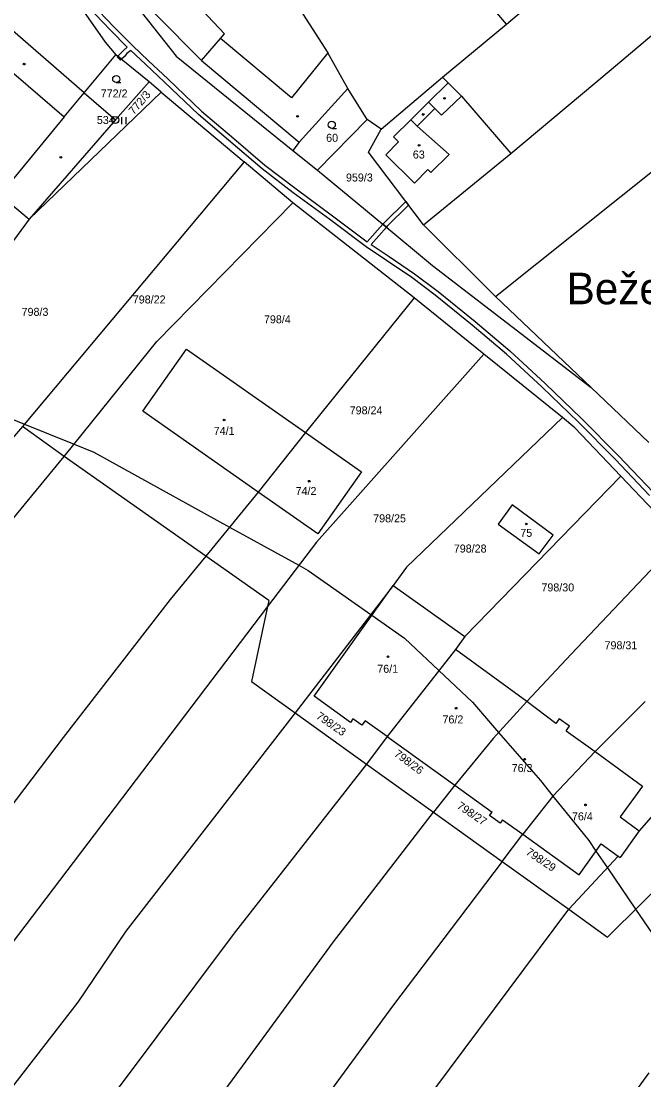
# Model space of a CAD drawing. Extents: x -749173 to -746119, y -1132678 to -1130338.
# Drawn here: x -747826.9 to -747694.7, y -1131323.7 to -1131098.8 of the extents above; entities that cross this region are included whole.
import ezdxf

# ---------------------------------------------------------------- set-up
doc = ezdxf.new("R2010")
doc.units = 0
for name, color, linetype in [('Vrstva 1', 7, 'Continuous'), ('Vrstva 15', 7, 'Continuous'), ('Vrstva 17', 7, 'Continuous'), ('Vrstva 18', 7, 'Continuous'), ('Vrstva 19', 7, 'Continuous'), ('Vrstva 24', 7, 'Continuous'), ('Vrstva 25', 7, 'Continuous'), ('Vrstva 3', 7, 'Continuous'), ('Vrstva 30', 7, 'Continuous'), ('Vrstva 37', 7, 'Continuous'), ('Vrstva 4', 7, 'Continuous'), ('Vrstva 52', 7, 'Continuous'), ('Vrstva 6', 7, 'Continuous')]:
    doc.layers.add(name, color=color, linetype=linetype)

msp = doc.modelspace()

# ---------------------------------------------------------------- linework, layer by layer
at = {"layer": 'Vrstva 1'}
for points in [[(-747702.08, -1131109.45), (-747662.38, -1131075.87)], [(-747723.91, -1131099.47), (-747741.27, -1131078.96)], [(-747723.91, -1131099.47), (-747702.76, -1131081.57)], [(-747774.37, -1131086), (-747761.8, -1131105.54)], [(-747819.11, -1131088.84), (-747809.11, -1131103.29)], [(-747808.48, -1131087.91), (-747794.01, -1131106.24)], [(-747813.56, -1131114.04), (-747828.66, -1131100.91)], [(-747737.5, -1131110.74), (-747723.91, -1131099.47)], [(-747809.11, -1131103.29), (-747806.82, -1131105.96)], [(-747757.6, -1131113.1), (-747761.8, -1131105.54)], [(-747813.56, -1131114.04), (-747806.82, -1131105.96)], [(-747799.76, -1131111.71), (-747806.82, -1131105.96)], [(-747794.01, -1131106.24), (-747769.24, -1131126.32)], [(-747722.98, -1131126.94), (-747702.08, -1131109.45)], [(-747806.92, -1131119.82), (-747799.76, -1131111.71)], [(-747797.21, -1131113.88), (-747799.76, -1131111.71)], [(-747750.5, -1131121.76), (-747737.5, -1131110.74)], [(-747737.5, -1131110.74), (-747736.31, -1131111.95)], [(-747733.44, -1131114.73), (-747736.31, -1131111.95)], [(-747825.19, -1131140.88), (-747797.21, -1131113.88)], [(-747813.56, -1131114.04), (-747806.92, -1131119.82)], [(-747797.21, -1131113.88), (-747779.57, -1131128.72)], [(-747757.6, -1131113.1), (-747767.92, -1131124.54)], [(-747753.47, -1131119.73), (-747757.6, -1131113.1)], [(-747733.44, -1131114.73), (-747722.98, -1131126.94)], [(-747806.92, -1131119.82), (-747825.19, -1131140.88)], [(-747753.47, -1131119.73), (-747764.01, -1131130.51)], [(-747750.5, -1131121.76), (-747753.47, -1131119.73)], [(-747753.2, -1131126.63), (-747750.5, -1131121.76)], [(-747767.92, -1131124.54), (-747769.24, -1131126.32)], [(-747769.24, -1131126.32), (-747764.01, -1131130.51)], [(-747741.53, -1131142.09), (-747753.2, -1131126.63)], [(-747741.53, -1131142.09), (-747722.98, -1131126.94)], [(-747779.57, -1131128.72), (-747826.65, -1131184.92)], [(-747769.22, -1131137.45), (-747779.57, -1131128.72)], [(-747764.01, -1131130.51), (-747750.16, -1131141.94)], [(-747743.52, -1131157.59), (-747769.22, -1131137.45)], [(-747825.19, -1131140.88), (-747830.35, -1131147.8)], [(-747750.16, -1131141.94), (-747739.59, -1131150.73)], [(-747727.01, -1131156.54), (-747741.53, -1131142.09)], [(-747739.59, -1131150.73), (-747705.95, -1131176.64)], [(-747726.24, -1131157.28), (-747727.01, -1131156.54)], [(-747705.95, -1131176.64), (-747726.24, -1131157.28)], [(-747728.7, -1131169.57), (-747743.52, -1131157.59)], [(-747801.07, -1131181.67), (-747791.81, -1131168.48)], [(-747791.81, -1131168.48), (-747766.58, -1131186.19)], [(-747712.03, -1131183.04), (-747728.7, -1131169.57)], [(-747705.95, -1131176.64), (-747693.71, -1131188.35)], [(-747776.59, -1131198.85), (-747801.07, -1131181.67)], [(-747709.37, -1131185.19), (-747712.03, -1131183.04)], [(-747826.65, -1131184.92), (-747857.38, -1131220.73)], [(-747817.77, -1131191.32), (-747826.65, -1131184.92)], [(-747766.58, -1131186.19), (-747776.59, -1131198.85)], [(-747766.58, -1131186.19), (-747754.69, -1131194.54)], [(-747699.59, -1131195.48), (-747709.37, -1131185.19)], [(-747787.74, -1131212.45), (-747817.77, -1131191.32)], [(-747754.69, -1131194.54), (-747763.95, -1131207.73)], [(-747686.96, -1131208.76), (-747699.59, -1131195.48)], [(-747763.95, -1131207.73), (-747776.59, -1131198.85)], [(-747722.72, -1131201.59), (-747725.64, -1131205.64)], [(-747714.02, -1131207.99), (-747722.72, -1131201.59)], [(-747725.64, -1131205.64), (-747716.93, -1131211.98)], [(-747716.93, -1131211.98), (-747714.02, -1131207.99)], [(-747774.35, -1131221.87), (-747787.74, -1131212.45)], [(-747764.72, -1131242.22), (-747747.94, -1131218.7)], [(-747747.94, -1131218.7), (-747732.77, -1131229.55)], [(-747774.35, -1131221.87), (-747774.62, -1131223.12)], [(-747774.62, -1131223.12), (-747778.06, -1131239.08)], [(-747732.77, -1131229.55), (-747734.74, -1131232.31)], [(-747734.74, -1131232.31), (-747749.21, -1131250.8)], [(-747719.59, -1131243.31), (-747734.74, -1131232.31)], [(-747778.06, -1131239.08), (-747768.78, -1131245.74)], [(-747757.01, -1131247.77), (-747764.72, -1131242.22)], [(-747719.59, -1131243.31), (-747726.72, -1131251.2)], [(-747713.41, -1131247.97), (-747719.59, -1131243.31)], [(-747768.78, -1131245.74), (-747753.62, -1131256.62)], [(-747756.49, -1131247.04), (-747757.01, -1131247.77)], [(-747754.62, -1131248.38), (-747756.49, -1131247.04)], [(-747712.71, -1131246.99), (-747713.41, -1131247.97)], [(-747710.52, -1131248.58), (-747712.71, -1131246.99)], [(-747753.92, -1131247.41), (-747754.62, -1131248.38)], [(-747749.21, -1131250.8), (-747753.92, -1131247.41)], [(-747711.22, -1131249.55), (-747710.52, -1131248.58)], [(-747711.22, -1131249.55), (-747705.1, -1131253.98)], [(-747749.21, -1131250.8), (-747734.88, -1131261.12)], [(-747726.72, -1131251.2), (-747734.88, -1131261.12)], [(-747705.1, -1131253.98), (-747714.03, -1131263.42)], [(-747705.1, -1131253.98), (-747695.01, -1131261.29)], [(-747753.62, -1131256.62), (-747739.39, -1131266.83)], [(-747734.88, -1131261.12), (-747726.94, -1131266.84)], [(-747695.01, -1131261.29), (-747699.76, -1131267.83)], [(-747714.03, -1131263.42), (-747720.46, -1131271.5)], [(-747739.39, -1131266.83), (-747724.81, -1131277.29)], [(-747727.47, -1131267.57), (-747726.94, -1131266.84)], [(-747725.23, -1131269.17), (-747727.47, -1131267.57)], [(-747724.71, -1131268.44), (-747725.23, -1131269.17)], [(-747724.71, -1131268.44), (-747720.46, -1131271.5)], [(-747699.76, -1131267.83), (-747695.74, -1131270.78)], [(-747720.46, -1131271.5), (-747708.48, -1131280.13)], [(-747695.74, -1131270.78), (-747699.8, -1131276.47)], [(-747708.48, -1131280.13), (-747703.77, -1131273.54)], [(-747703.77, -1131273.54), (-747700.19, -1131276.18)], [(-747700.19, -1131276.18), (-747699.8, -1131276.47)], [(-747724.81, -1131277.29), (-747710.63, -1131287.46)], [(-747702.43, -1131293.35), (-747687.96, -1131278.99)], [(-747710.63, -1131287.46), (-747702.43, -1131293.35)]]:
    msp.add_lwpolyline(points, dxfattribs=at)
at = {"layer": 'Vrstva 24'}
msp.add_line((-747806.97, -1131119.82), (-747806.87, -1131119.82), dxfattribs=at)
msp.add_circle((-747806.92, -1131119.82), 0.756, dxfattribs=at)
at = {"layer": 'Vrstva 25'}
for p, q in [((-747806.74, -1131111.88), (-747805.74, -1131111.88)), ((-747805.6, -1131119.2), (-747805.6, -1131120.7)), ((-747804.6, -1131120.7), (-747804.6, -1131119.2)), ((-747760.98, -1131121.6), (-747759.98, -1131121.6))]:
    msp.add_line(p, q, dxfattribs=at)
for centre, radius in [((-747826.29, -1131107.95), 0.175), ((-747806.74, -1131111.13), 0.75), ((-747737.07, -1131115.22), 0.175), ((-747768.25, -1131119.04), 0.175), ((-747741.58, -1131118.65), 0.175), ((-747760.98, -1131120.85), 0.75), ((-747742.44, -1131125.22), 0.175), ((-747818.51, -1131127.76), 0.175), ((-747783.84, -1131183.56), 0.175), ((-747765.78, -1131196.54), 0.175), ((-747719.69, -1131205.62), 0.175), ((-747749.04, -1131233.82), 0.175), ((-747734.59, -1131244.75), 0.175), ((-747720.04, -1131255.59), 0.175), ((-747707.12, -1131265.29), 0.175)]:
    msp.add_circle(centre, radius, dxfattribs=at)
at = {"layer": 'Vrstva 3'}
for points in [[(-747788.64, -1131107.19), (-747808.1, -1131087.52)], [(-747783.76, -1131101.49), (-747796.8, -1131087.65)], [(-747788.64, -1131107.19), (-747784.63, -1131102.5)], [(-747784.63, -1131102.5), (-747783.76, -1131101.49)], [(-747747.9, -1131123.42), (-747744.21, -1131119.77)], [(-747744.21, -1131119.77), (-747742.88, -1131121.12)], [(-747742.88, -1131121.12), (-747736.04, -1131127.17)], [(-747746.83, -1131124.48), (-747747.9, -1131123.42)], [(-747749.52, -1131127.2), (-747746.83, -1131124.48)], [(-747743.43, -1131133.22), (-747749.52, -1131127.2)], [(-747739.95, -1131130.99), (-747736.04, -1131127.17)], [(-747743.43, -1131133.22), (-747740.6, -1131130.35)], [(-747740.6, -1131130.35), (-747739.95, -1131130.99)], [(-747801.07, -1131181.67), (-747791.81, -1131168.48)], [(-747791.81, -1131168.48), (-747766.58, -1131186.19)], [(-747776.59, -1131198.85), (-747801.07, -1131181.67)], [(-747766.58, -1131186.19), (-747754.69, -1131194.54)], [(-747754.69, -1131194.54), (-747763.95, -1131207.73)], [(-747763.95, -1131207.73), (-747776.59, -1131198.85)], [(-747722.72, -1131201.59), (-747725.64, -1131205.64)], [(-747714.02, -1131207.99), (-747722.72, -1131201.59)], [(-747725.64, -1131205.64), (-747716.93, -1131211.98)], [(-747716.93, -1131211.98), (-747714.02, -1131207.99)], [(-747764.72, -1131242.22), (-747747.94, -1131218.7)], [(-747747.94, -1131218.7), (-747732.77, -1131229.55)], [(-747732.77, -1131229.55), (-747734.74, -1131232.31)], [(-747719.59, -1131243.31), (-747734.74, -1131232.31)], [(-747757.01, -1131247.77), (-747764.72, -1131242.22)], [(-747713.41, -1131247.97), (-747719.59, -1131243.31)], [(-747756.49, -1131247.04), (-747757.01, -1131247.77)], [(-747754.62, -1131248.38), (-747756.49, -1131247.04)], [(-747712.71, -1131246.99), (-747713.41, -1131247.97)], [(-747710.52, -1131248.58), (-747712.71, -1131246.99)], [(-747753.92, -1131247.41), (-747754.62, -1131248.38)], [(-747749.21, -1131250.8), (-747753.92, -1131247.41)], [(-747711.22, -1131249.55), (-747710.52, -1131248.58)], [(-747711.22, -1131249.55), (-747705.1, -1131253.98)], [(-747749.21, -1131250.8), (-747734.88, -1131261.12)], [(-747705.1, -1131253.98), (-747695.01, -1131261.29)], [(-747734.88, -1131261.12), (-747726.94, -1131266.84)], [(-747695.01, -1131261.29), (-747699.76, -1131267.83)], [(-747727.47, -1131267.57), (-747726.94, -1131266.84)], [(-747725.23, -1131269.17), (-747727.47, -1131267.57)], [(-747724.71, -1131268.44), (-747725.23, -1131269.17)], [(-747724.71, -1131268.44), (-747720.46, -1131271.5)], [(-747699.76, -1131267.83), (-747695.74, -1131270.78)], [(-747720.46, -1131271.5), (-747708.48, -1131280.13)], [(-747695.74, -1131270.78), (-747699.8, -1131276.47)], [(-747708.48, -1131280.13), (-747703.77, -1131273.54)], [(-747703.77, -1131273.54), (-747700.19, -1131276.18)], [(-747700.19, -1131276.18), (-747699.8, -1131276.47)]]:
    msp.add_lwpolyline(points, dxfattribs=at)
at = {"layer": 'Vrstva 30'}
for points in [[(-747807.96, -1131100.76), (-747812.77, -1131095.73)], [(-747812.01, -1131095.09), (-747807.24, -1131100.06)], [(-747804.4, -1131104.34), (-747807.96, -1131100.76)], [(-747807.24, -1131100.06), (-747803.31, -1131104.01)], [(-747805.81, -1131105.73), (-747805.16, -1131104.98)], [(-747805.16, -1131104.98), (-747804.4, -1131104.34)], [(-747804.46, -1131105.7), (-747805.09, -1131106.41)], [(-747803.67, -1131105.04), (-747804.46, -1131105.7)], [(-747800.55, -1131107.95), (-747803.67, -1131105.04)], [(-747803.31, -1131104.01), (-747799.87, -1131107.23)], [(-747806.51, -1131106.4), (-747806.4, -1131106.3)], [(-747805.81, -1131107.12), (-747806.51, -1131106.4)], [(-747806.4, -1131106.3), (-747805.81, -1131105.73)], [(-747805.62, -1131106.94), (-747806.4, -1131106.3)], [(-747806.4, -1131106.3), (-747805.62, -1131106.94)], [(-747805.62, -1131106.94), (-747805.81, -1131107.12)], [(-747805.09, -1131106.41), (-747805.62, -1131106.94)], [(-747796.47, -1131111.82), (-747800.55, -1131107.95)], [(-747799.87, -1131107.23), (-747795.78, -1131111.09)], [(-747789.3, -1131118.68), (-747796.47, -1131111.82)], [(-747795.78, -1131111.09), (-747788.64, -1131117.94)], [(-747782.92, -1131124.1), (-747789.3, -1131118.68)], [(-747788.64, -1131117.94), (-747782.27, -1131123.34)], [(-747782.27, -1131123.34), (-747775.17, -1131129.41)], [(-747775.79, -1131130.19), (-747782.92, -1131124.1)], [(-747769.15, -1131135.27), (-747775.79, -1131130.19)], [(-747775.17, -1131129.41), (-747768.55, -1131134.47)], [(-747768.55, -1131134.47), (-747760.82, -1131140.16)], [(-747761.42, -1131140.96), (-747769.15, -1131135.27)], [(-747749.95, -1131141.72), (-747745.28, -1131137.13)], [(-747745.28, -1131137.13), (-747744.68, -1131137.92)], [(-747744.68, -1131137.92), (-747749.23, -1131142.4)], [(-747753.7, -1131146.78), (-747761.42, -1131140.96)], [(-747760.82, -1131140.16), (-747753.48, -1131145.69)], [(-747753.48, -1131145.69), (-747750.16, -1131141.94)], [(-747749.39, -1131142.58), (-747752.65, -1131146.27)], [(-747750.16, -1131141.94), (-747749.95, -1131141.72)], [(-747750.16, -1131141.94), (-747749.39, -1131142.58)], [(-747749.39, -1131142.58), (-747750.16, -1131141.94)], [(-747749.23, -1131142.4), (-747749.39, -1131142.58)], [(-747749.34, -1131149.64), (-747753.7, -1131146.78)], [(-747752.65, -1131146.27), (-747748.8, -1131148.8)], [(-747744.02, -1131153.3), (-747749.34, -1131149.64)], [(-747748.8, -1131148.8), (-747743.44, -1131152.48)], [(-747743.44, -1131152.48), (-747738.42, -1131156.22)], [(-747739.04, -1131157), (-747744.02, -1131153.3)], [(-747731.21, -1131163.37), (-747739.04, -1131157)], [(-747738.42, -1131156.22), (-747730.57, -1131162.6)], [(-747723.88, -1131169.59), (-747731.21, -1131163.37)], [(-747730.57, -1131162.6), (-747723.22, -1131168.85)], [(-747716.34, -1131176.54), (-747723.88, -1131169.59)], [(-747723.22, -1131168.85), (-747715.66, -1131175.81)], [(-747708.67, -1131183.91), (-747716.34, -1131176.54)], [(-747715.66, -1131175.81), (-747707.97, -1131183.19)], [(-747700.84, -1131191.84), (-747708.67, -1131183.91)], [(-747707.97, -1131183.19), (-747700.12, -1131191.14)], [(-747700.12, -1131191.14), (-747692.78, -1131198.87)], [(-747693.52, -1131199.55), (-747700.84, -1131191.84)]]:
    msp.add_lwpolyline(points, dxfattribs=at)
at = {"layer": 'Vrstva 37'}
for centre in [(-747742.44, -1131125.22), (-747765.78, -1131196.54), (-747719.69, -1131205.62), (-747749.04, -1131233.82)]:
    msp.add_circle(centre, 0.175, dxfattribs=at)
at = {"layer": 'Vrstva 4'}
for points in [[(-747788.64, -1131107.19), (-747808.1, -1131087.52)], [(-747783.76, -1131101.49), (-747796.8, -1131087.65)], [(-747788.64, -1131107.19), (-747784.63, -1131102.5)], [(-747784.63, -1131102.5), (-747783.76, -1131101.49)], [(-747769.52, -1131115.12), (-747784.63, -1131102.5)], [(-747833.62, -1131105.57), (-747817.82, -1131119.12)], [(-747761.8, -1131105.54), (-747769.52, -1131115.12)], [(-747788.64, -1131107.19), (-747767.92, -1131124.54)], [(-747740.46, -1131116.05), (-747736.31, -1131111.95)], [(-747817.82, -1131119.12), (-747813.56, -1131114.04)], [(-747744.21, -1131119.77), (-747740.46, -1131116.05)], [(-747740.46, -1131116.05), (-747739.12, -1131117.4)], [(-747737.72, -1131118.82), (-747733.44, -1131114.73)], [(-747817.82, -1131119.12), (-747831.4, -1131135.72)], [(-747739.12, -1131117.4), (-747742.88, -1131121.12)], [(-747739.12, -1131117.4), (-747737.72, -1131118.82)], [(-747747.9, -1131123.42), (-747744.21, -1131119.77)], [(-747744.21, -1131119.77), (-747742.88, -1131121.12)], [(-747742.88, -1131121.12), (-747736.04, -1131127.17)], [(-747746.83, -1131124.48), (-747747.9, -1131123.42)], [(-747749.52, -1131127.2), (-747746.83, -1131124.48)], [(-747743.43, -1131133.22), (-747749.52, -1131127.2)], [(-747739.95, -1131130.99), (-747736.04, -1131127.17)], [(-747743.43, -1131133.22), (-747740.6, -1131130.35)], [(-747740.6, -1131130.35), (-747739.95, -1131130.99)], [(-747831.4, -1131135.72), (-747825.19, -1131140.88)]]:
    msp.add_lwpolyline(points, dxfattribs=at)
at = {"layer": 'Vrstva 52'}
msp.add_lwpolyline([(-747851.21, -1131174.25), (-747826.21, -1131184.4), (-747815.66, -1131188.68), (-747811.5, -1131190.37), (-747782.68, -1131206.28), (-747767.97, -1131214.41), (-747766, -1131215.5), (-747752.69, -1131224.86), (-747752.45, -1131225.03), (-747745.56, -1131229.87), (-747738.24, -1131236.78), (-747731.12, -1131243.5), (-747725.56, -1131249.91), (-747716.69, -1131260.12), (-747714.03, -1131263.42), (-747706.44, -1131272.87), (-747704.9, -1131275.12), (-747702.48, -1131278.66), (-747696.48, -1131287.44), (-747682.34, -1131308.14), (-747672.55, -1131322.46), (-747672.44, -1131322.62), (-747663.5, -1131335.37)], dxfattribs=at)
at = {"layer": 'Vrstva 6'}
for points in [[(-747726.24, -1131157.28), (-747690.81, -1131128.96)], [(-747798.15, -1131166.84), (-747769.22, -1131137.45)], [(-747743.52, -1131157.59), (-747766.58, -1131186.19)], [(-747817.77, -1131191.32), (-747798.15, -1131166.84)], [(-747756.55, -1131200.89), (-747728.7, -1131169.57)], [(-747712.03, -1131183.04), (-747745.11, -1131214.77)], [(-747849.87, -1131230.22), (-747817.77, -1131191.32)], [(-747699.59, -1131195.48), (-747732.77, -1131229.55)], [(-747776.59, -1131198.85), (-747787.74, -1131212.45)], [(-747764.24, -1131209.52), (-747756.55, -1131200.89)], [(-747686.96, -1131208.76), (-747710.17, -1131233.27)], [(-747764.24, -1131209.52), (-747774.62, -1131223.12)], [(-747787.74, -1131212.45), (-747795.27, -1131221.64)], [(-747745.11, -1131214.77), (-747747.94, -1131218.7)], [(-747747.94, -1131218.7), (-747768.78, -1131245.74)], [(-747795.27, -1131221.64), (-747818.02, -1131250.97)], [(-747774.62, -1131223.12), (-747846.71, -1131318.11)], [(-747710.17, -1131233.27), (-747719.59, -1131243.31)], [(-747705.1, -1131253.98), (-747694.48, -1131243.3)], [(-747768.78, -1131245.74), (-747804.7, -1131292.12)], [(-747818.02, -1131250.97), (-747832.91, -1131270.59)], [(-747749.21, -1131250.8), (-747753.62, -1131256.62)], [(-747753.62, -1131256.62), (-747781.73, -1131292.56)], [(-747683.08, -1131256.39), (-747695.74, -1131270.78)], [(-747734.88, -1131261.12), (-747739.39, -1131266.83)], [(-747760.62, -1131294.4), (-747739.39, -1131266.83)], [(-747724.81, -1131277.29), (-747720.46, -1131271.5)], [(-747700.19, -1131276.18), (-747710.63, -1131287.46)], [(-747724.81, -1131277.29), (-747735.67, -1131291.6)], [(-747748.68, -1131338.4), (-747710.63, -1131287.46)], [(-747804.7, -1131292.12), (-747814.92, -1131307.18)], [(-747735.67, -1131291.6), (-747747.86, -1131307.75)], [(-747781.73, -1131292.56), (-747831.18, -1131358.67)], [(-747784.2, -1131326.61), (-747760.62, -1131294.4)], [(-747814.92, -1131307.18), (-747846.34, -1131347.72)], [(-747747.86, -1131307.75), (-747777.73, -1131348.55)], [(-747693.71, -1131322.2), (-747729.49, -1131371.5)]]:
    msp.add_lwpolyline(points, dxfattribs=at)

# ---------------------------------------------------------------- texts
at = {"layer": 'Vrstva 15'}
msp.add_text('Bežerovice', height=6.7, dxfattribs=at).set_placement((-747711.12, -1131158.96))
at = {"layer": 'Vrstva 17'}
msp.add_text('534', height=1.7, dxfattribs=at).set_placement((-747810.85, -1131120.67))
at = {"layer": 'Vrstva 18'}
for s, p in [('772/2', (-747810.03, -1131115.04)), ('60', (-747762.18, -1131124.46)), ('959/3', (-747757.97, -1131132.89)), ('798/22', (-747803.22, -1131158.79)), ('798/3', (-747826.83, -1131161.42)), ('798/4', (-747775.38, -1131163.01)), ('798/24', (-747757.18, -1131182.34)), ('798/25', (-747752.19, -1131205.28)), ('798/28', (-747735.08, -1131211.69)), ('798/30', (-747716.48, -1131219.95)), ('798/31', (-747703.08, -1131232.24))]:
    msp.add_text(s, height=1.7, dxfattribs=at).set_placement(p)
for s, rotation, p in [('772/3', 49.4577, (-747803, -1131118.83)), ('798/23', 325.271, (-747764.44, -1131246.8)), ('798/26', 323.2595, (-747747.89, -1131254.77)), ('798/27', 326.3099, (-747734.57, -1131265.9)), ('798/29', 326.1429, (-747719.91, -1131275.69))]:
    msp.add_text(s, height=1.7, rotation=rotation, dxfattribs=at).set_placement(p)
at = {"layer": 'Vrstva 19'}
for s, p in [('63', (-747743.78, -1131128.01)), ('74/1', (-747786.04, -1131186.7)), ('74/2', (-747768.66, -1131199.47)), ('75', (-747720.96, -1131208.36)), ('76/1', (-747751.33, -1131237.23)), ('76/2', (-747737.48, -1131247.99)), ('76/3', (-747722.79, -1131258.32)), ('76/4', (-747710, -1131268.57))]:
    msp.add_text(s, height=1.7, dxfattribs=at).set_placement(p)

doc.saveas('drawing.dxf')
